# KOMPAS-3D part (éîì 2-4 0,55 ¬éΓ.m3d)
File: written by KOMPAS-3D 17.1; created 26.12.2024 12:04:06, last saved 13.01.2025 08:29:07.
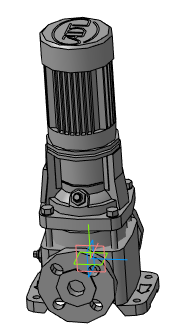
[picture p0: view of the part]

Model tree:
1. Операция без истории:3  (labels: ВМН 2-4 0,55 кВт)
